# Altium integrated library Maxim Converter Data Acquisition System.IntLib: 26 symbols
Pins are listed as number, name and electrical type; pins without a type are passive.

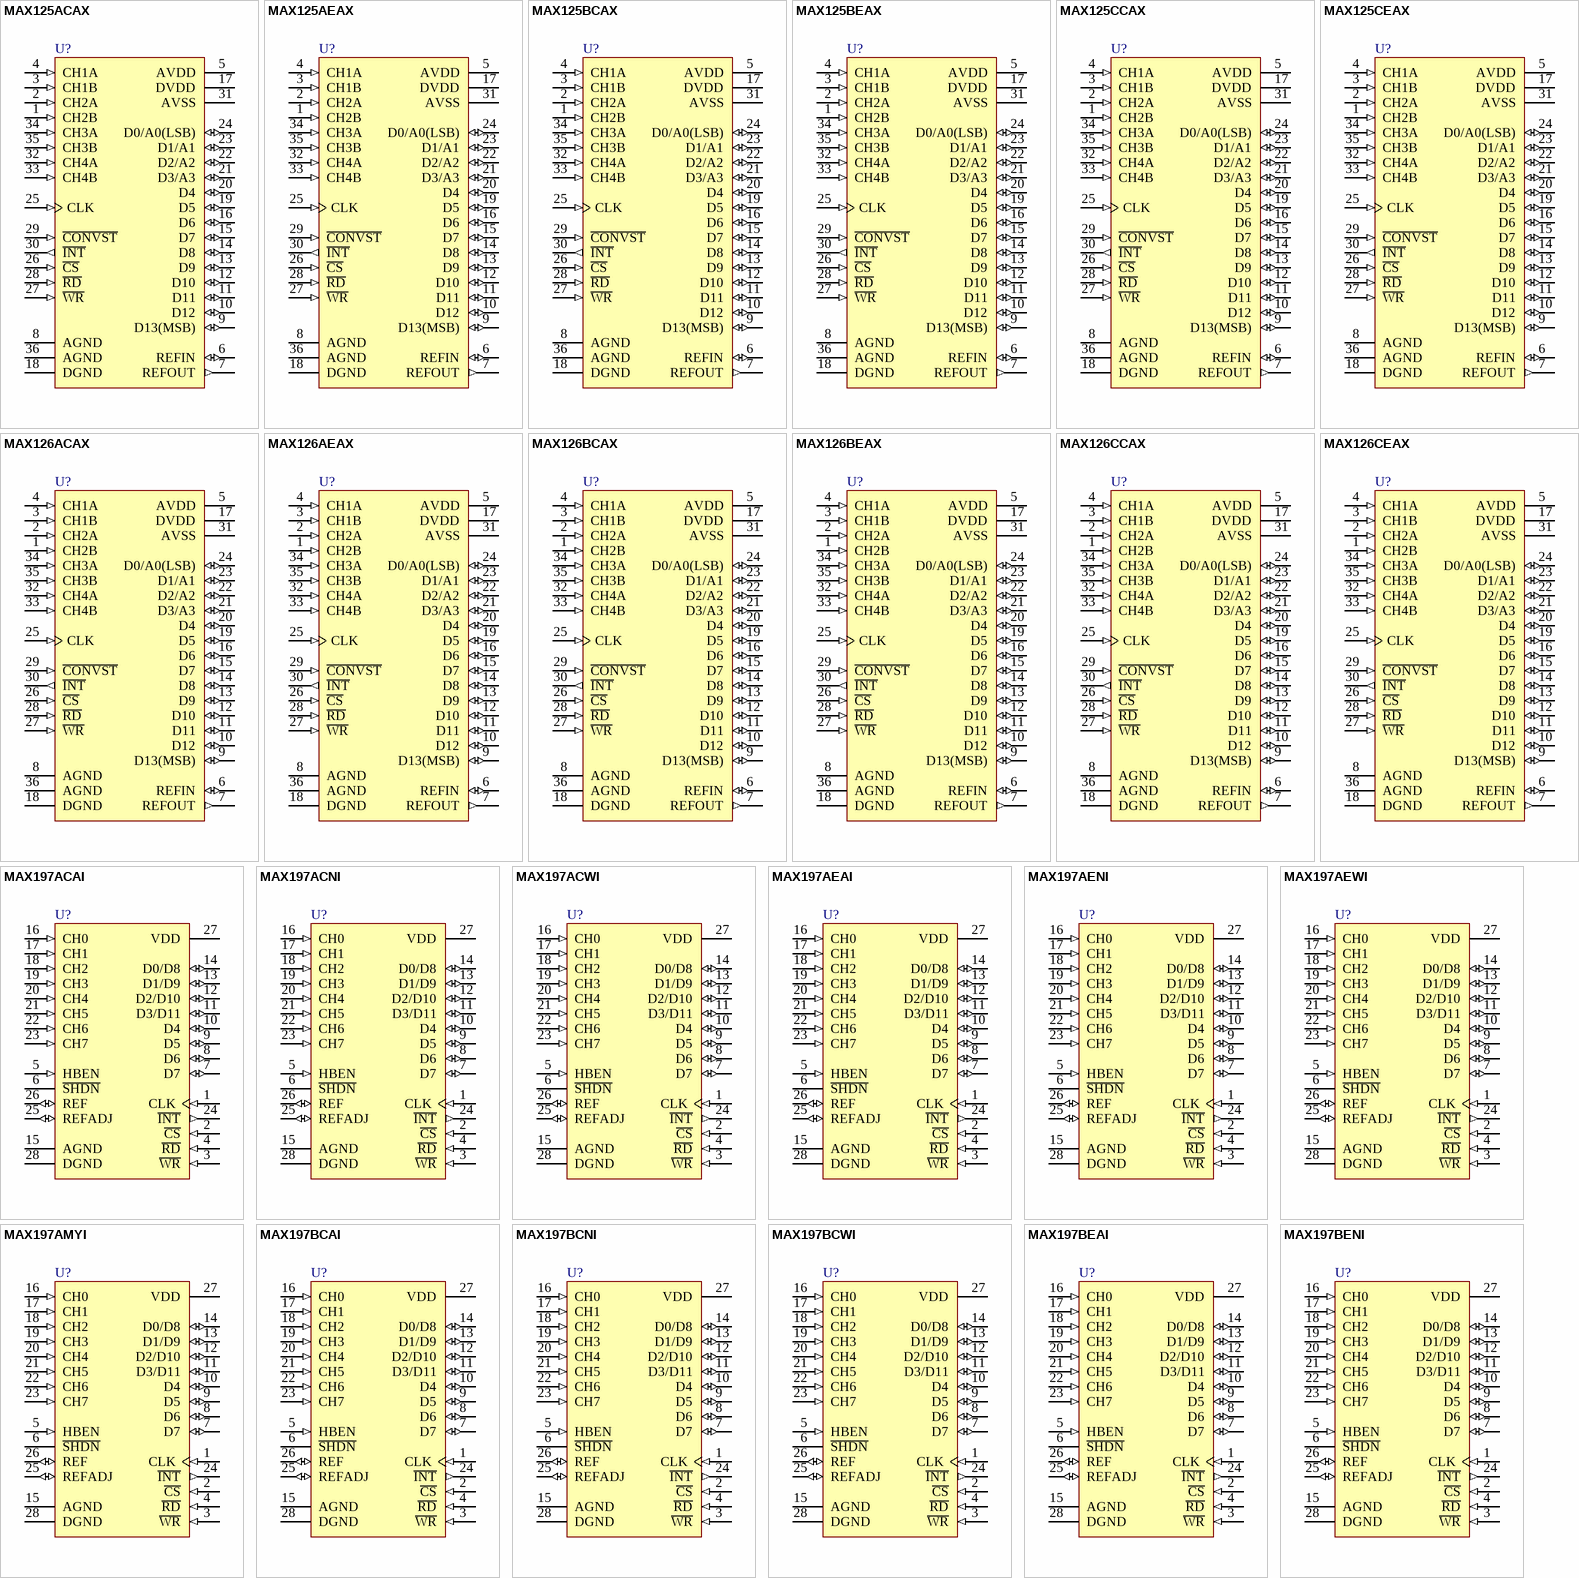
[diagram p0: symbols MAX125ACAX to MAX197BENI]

## MAX125ACAX
designator U?
2x4-Channel, Simultaneous-Sampling 14-Bit DAS
footprint SSOP36_N (SOP, 36-Leads, Body 15.4x7.5mm, Pitch 0.8mm, IPC Medium Density)
footprint SSOP36_L (SOP, 36-Leads, Body 15.4x7.5mm, Pitch 0.8mm, IPC High Density)
footprint SSOP36_M (SOP, 36-Leads, Body 15.4x7.5mm, Pitch 0.8mm, IPC Low Density)
3D model SSOP36 (36-Pin Small Outline Package 0.8 mm Pitch)
pins: 1 CH2B (in), 2 CH2A (in), 3 CH1B (in), 4 CH1A (in), 5 AVDD (power), 6 REFIN (io), 7 REFOUT (out), 8 AGND (power), 9 D13(MSB) (io), 10 D12 (io), 11 D11 (io), 12 D10 (io), 13 D9 (io), 14 D8 (io), 15 D7 (io), 16 D6 (io), 17 DVDD (power), 18 DGND (power), 19 D5 (io), 20 D4 (io), 21 D3/A3 (io), 22 D2/A2 (io), 23 D1/A1 (io), 24 D0/A0(LSB) (io), 25 CLK (in), 26 ~{CS} (in), 27 ~{WR} (in), 28 ~{RD} (in), 29 ~{CONVST} (in), 30 ~{INT} (out), 31 AVSS (power), 32 CH4A (in), 33 CH4B (in), 34 CH3A (in), 35 CH3B (in), 36 AGND (power)

## MAX125AEAX
designator U?
2x4-Channel, Simultaneous-Sampling 14-Bit DAS
footprint SSOP36_N (SOP, 36-Leads, Body 15.4x7.5mm, Pitch 0.8mm, IPC Medium Density)
footprint SSOP36_L (SOP, 36-Leads, Body 15.4x7.5mm, Pitch 0.8mm, IPC High Density)
footprint SSOP36_M (SOP, 36-Leads, Body 15.4x7.5mm, Pitch 0.8mm, IPC Low Density)
3D model SSOP36 (36-Pin Small Outline Package 0.8 mm Pitch)
pins: 1 CH2B (in), 2 CH2A (in), 3 CH1B (in), 4 CH1A (in), 5 AVDD (power), 6 REFIN (io), 7 REFOUT (out), 8 AGND (power), 9 D13(MSB) (io), 10 D12 (io), 11 D11 (io), 12 D10 (io), 13 D9 (io), 14 D8 (io), 15 D7 (io), 16 D6 (io), 17 DVDD (power), 18 DGND (power), 19 D5 (io), 20 D4 (io), 21 D3/A3 (io), 22 D2/A2 (io), 23 D1/A1 (io), 24 D0/A0(LSB) (io), 25 CLK (in), 26 ~{CS} (in), 27 ~{WR} (in), 28 ~{RD} (in), 29 ~{CONVST} (in), 30 ~{INT} (out), 31 AVSS (power), 32 CH4A (in), 33 CH4B (in), 34 CH3A (in), 35 CH3B (in), 36 AGND (power)

## MAX125BCAX
designator U?
2x4-Channel, Simultaneous-Sampling 14-Bit DAS
footprint SSOP36_N (SOP, 36-Leads, Body 15.4x7.5mm, Pitch 0.8mm, IPC Medium Density)
footprint SSOP36_L (SOP, 36-Leads, Body 15.4x7.5mm, Pitch 0.8mm, IPC High Density)
footprint SSOP36_M (SOP, 36-Leads, Body 15.4x7.5mm, Pitch 0.8mm, IPC Low Density)
3D model SSOP36 (36-Pin Small Outline Package 0.8 mm Pitch)
pins: 1 CH2B (in), 2 CH2A (in), 3 CH1B (in), 4 CH1A (in), 5 AVDD (power), 6 REFIN (io), 7 REFOUT (out), 8 AGND (power), 9 D13(MSB) (io), 10 D12 (io), 11 D11 (io), 12 D10 (io), 13 D9 (io), 14 D8 (io), 15 D7 (io), 16 D6 (io), 17 DVDD (power), 18 DGND (power), 19 D5 (io), 20 D4 (io), 21 D3/A3 (io), 22 D2/A2 (io), 23 D1/A1 (io), 24 D0/A0(LSB) (io), 25 CLK (in), 26 ~{CS} (in), 27 ~{WR} (in), 28 ~{RD} (in), 29 ~{CONVST} (in), 30 ~{INT} (out), 31 AVSS (power), 32 CH4A (in), 33 CH4B (in), 34 CH3A (in), 35 CH3B (in), 36 AGND (power)

## MAX125BEAX
designator U?
2x4-Channel, Simultaneous-Sampling 14-Bit DAS
footprint SSOP36_N (SOP, 36-Leads, Body 15.4x7.5mm, Pitch 0.8mm, IPC Medium Density)
footprint SSOP36_L (SOP, 36-Leads, Body 15.4x7.5mm, Pitch 0.8mm, IPC High Density)
footprint SSOP36_M (SOP, 36-Leads, Body 15.4x7.5mm, Pitch 0.8mm, IPC Low Density)
3D model SSOP36 (36-Pin Small Outline Package 0.8 mm Pitch)
pins: 1 CH2B (in), 2 CH2A (in), 3 CH1B (in), 4 CH1A (in), 5 AVDD (power), 6 REFIN (io), 7 REFOUT (out), 8 AGND (power), 9 D13(MSB) (io), 10 D12 (io), 11 D11 (io), 12 D10 (io), 13 D9 (io), 14 D8 (io), 15 D7 (io), 16 D6 (io), 17 DVDD (power), 18 DGND (power), 19 D5 (io), 20 D4 (io), 21 D3/A3 (io), 22 D2/A2 (io), 23 D1/A1 (io), 24 D0/A0(LSB) (io), 25 CLK (in), 26 ~{CS} (in), 27 ~{WR} (in), 28 ~{RD} (in), 29 ~{CONVST} (in), 30 ~{INT} (out), 31 AVSS (power), 32 CH4A (in), 33 CH4B (in), 34 CH3A (in), 35 CH3B (in), 36 AGND (power)

## MAX125CCAX
designator U?
2x4-Channel, Simultaneous-Sampling 14-Bit DAS
footprint SSOP36_N (SOP, 36-Leads, Body 15.4x7.5mm, Pitch 0.8mm, IPC Medium Density)
footprint SSOP36_L (SOP, 36-Leads, Body 15.4x7.5mm, Pitch 0.8mm, IPC High Density)
footprint SSOP36_M (SOP, 36-Leads, Body 15.4x7.5mm, Pitch 0.8mm, IPC Low Density)
3D model SSOP36 (36-Pin Small Outline Package 0.8 mm Pitch)
pins: 1 CH2B (in), 2 CH2A (in), 3 CH1B (in), 4 CH1A (in), 5 AVDD (power), 6 REFIN (io), 7 REFOUT (out), 8 AGND (power), 9 D13(MSB) (io), 10 D12 (io), 11 D11 (io), 12 D10 (io), 13 D9 (io), 14 D8 (io), 15 D7 (io), 16 D6 (io), 17 DVDD (power), 18 DGND (power), 19 D5 (io), 20 D4 (io), 21 D3/A3 (io), 22 D2/A2 (io), 23 D1/A1 (io), 24 D0/A0(LSB) (io), 25 CLK (in), 26 ~{CS} (in), 27 ~{WR} (in), 28 ~{RD} (in), 29 ~{CONVST} (in), 30 ~{INT} (out), 31 AVSS (power), 32 CH4A (in), 33 CH4B (in), 34 CH3A (in), 35 CH3B (in), 36 AGND (power)

## MAX125CEAX
designator U?
2x4-Channel, Simultaneous-Sampling 14-Bit DAS
footprint SSOP36_N (SOP, 36-Leads, Body 15.4x7.5mm, Pitch 0.8mm, IPC Medium Density)
footprint SSOP36_L (SOP, 36-Leads, Body 15.4x7.5mm, Pitch 0.8mm, IPC High Density)
footprint SSOP36_M (SOP, 36-Leads, Body 15.4x7.5mm, Pitch 0.8mm, IPC Low Density)
3D model SSOP36 (36-Pin Small Outline Package 0.8 mm Pitch)
pins: 1 CH2B (in), 2 CH2A (in), 3 CH1B (in), 4 CH1A (in), 5 AVDD (power), 6 REFIN (io), 7 REFOUT (out), 8 AGND (power), 9 D13(MSB) (io), 10 D12 (io), 11 D11 (io), 12 D10 (io), 13 D9 (io), 14 D8 (io), 15 D7 (io), 16 D6 (io), 17 DVDD (power), 18 DGND (power), 19 D5 (io), 20 D4 (io), 21 D3/A3 (io), 22 D2/A2 (io), 23 D1/A1 (io), 24 D0/A0(LSB) (io), 25 CLK (in), 26 ~{CS} (in), 27 ~{WR} (in), 28 ~{RD} (in), 29 ~{CONVST} (in), 30 ~{INT} (out), 31 AVSS (power), 32 CH4A (in), 33 CH4B (in), 34 CH3A (in), 35 CH3B (in), 36 AGND (power)

## MAX126ACAX
designator U?
2x4-Channel, Simultaneous-Sampling 14-Bit DAS
footprint SSOP36_N (SOP, 36-Leads, Body 15.4x7.5mm, Pitch 0.8mm, IPC Medium Density)
footprint SSOP36_L (SOP, 36-Leads, Body 15.4x7.5mm, Pitch 0.8mm, IPC High Density)
footprint SSOP36_M (SOP, 36-Leads, Body 15.4x7.5mm, Pitch 0.8mm, IPC Low Density)
3D model SSOP36 (36-Pin Small Outline Package 0.8 mm Pitch)
pins: 1 CH2B (in), 2 CH2A (in), 3 CH1B (in), 4 CH1A (in), 5 AVDD (power), 6 REFIN (io), 7 REFOUT (out), 8 AGND (power), 9 D13(MSB) (io), 10 D12 (io), 11 D11 (io), 12 D10 (io), 13 D9 (io), 14 D8 (io), 15 D7 (io), 16 D6 (io), 17 DVDD (power), 18 DGND (power), 19 D5 (io), 20 D4 (io), 21 D3/A3 (io), 22 D2/A2 (io), 23 D1/A1 (io), 24 D0/A0(LSB) (io), 25 CLK (in), 26 ~{CS} (in), 27 ~{WR} (in), 28 ~{RD} (in), 29 ~{CONVST} (in), 30 ~{INT} (out), 31 AVSS (power), 32 CH4A (in), 33 CH4B (in), 34 CH3A (in), 35 CH3B (in), 36 AGND (power)

## MAX126AEAX
designator U?
2x4-Channel, Simultaneous-Sampling 14-Bit DAS
footprint SSOP36_N (SOP, 36-Leads, Body 15.4x7.5mm, Pitch 0.8mm, IPC Medium Density)
footprint SSOP36_L (SOP, 36-Leads, Body 15.4x7.5mm, Pitch 0.8mm, IPC High Density)
footprint SSOP36_M (SOP, 36-Leads, Body 15.4x7.5mm, Pitch 0.8mm, IPC Low Density)
3D model SSOP36 (36-Pin Small Outline Package 0.8 mm Pitch)
pins: 1 CH2B (in), 2 CH2A (in), 3 CH1B (in), 4 CH1A (in), 5 AVDD (power), 6 REFIN (io), 7 REFOUT (out), 8 AGND (power), 9 D13(MSB) (io), 10 D12 (io), 11 D11 (io), 12 D10 (io), 13 D9 (io), 14 D8 (io), 15 D7 (io), 16 D6 (io), 17 DVDD (power), 18 DGND (power), 19 D5 (io), 20 D4 (io), 21 D3/A3 (io), 22 D2/A2 (io), 23 D1/A1 (io), 24 D0/A0(LSB) (io), 25 CLK (in), 26 ~{CS} (in), 27 ~{WR} (in), 28 ~{RD} (in), 29 ~{CONVST} (in), 30 ~{INT} (out), 31 AVSS (power), 32 CH4A (in), 33 CH4B (in), 34 CH3A (in), 35 CH3B (in), 36 AGND (power)

## MAX126BCAX
designator U?
2x4-Channel, Simultaneous-Sampling 14-Bit DAS
footprint SSOP36_N (SOP, 36-Leads, Body 15.4x7.5mm, Pitch 0.8mm, IPC Medium Density)
footprint SSOP36_L (SOP, 36-Leads, Body 15.4x7.5mm, Pitch 0.8mm, IPC High Density)
footprint SSOP36_M (SOP, 36-Leads, Body 15.4x7.5mm, Pitch 0.8mm, IPC Low Density)
3D model SSOP36 (36-Pin Small Outline Package 0.8 mm Pitch)
pins: 1 CH2B (in), 2 CH2A (in), 3 CH1B (in), 4 CH1A (in), 5 AVDD (power), 6 REFIN (io), 7 REFOUT (out), 8 AGND (power), 9 D13(MSB) (io), 10 D12 (io), 11 D11 (io), 12 D10 (io), 13 D9 (io), 14 D8 (io), 15 D7 (io), 16 D6 (io), 17 DVDD (power), 18 DGND (power), 19 D5 (io), 20 D4 (io), 21 D3/A3 (io), 22 D2/A2 (io), 23 D1/A1 (io), 24 D0/A0(LSB) (io), 25 CLK (in), 26 ~{CS} (in), 27 ~{WR} (in), 28 ~{RD} (in), 29 ~{CONVST} (in), 30 ~{INT} (out), 31 AVSS (power), 32 CH4A (in), 33 CH4B (in), 34 CH3A (in), 35 CH3B (in), 36 AGND (power)

## MAX126BEAX
designator U?
2x4-Channel, Simultaneous-Sampling 14-Bit DAS
footprint SSOP36_N (SOP, 36-Leads, Body 15.4x7.5mm, Pitch 0.8mm, IPC Medium Density)
footprint SSOP36_L (SOP, 36-Leads, Body 15.4x7.5mm, Pitch 0.8mm, IPC High Density)
footprint SSOP36_M (SOP, 36-Leads, Body 15.4x7.5mm, Pitch 0.8mm, IPC Low Density)
3D model SSOP36 (36-Pin Small Outline Package 0.8 mm Pitch)
pins: 1 CH2B (in), 2 CH2A (in), 3 CH1B (in), 4 CH1A (in), 5 AVDD (power), 6 REFIN (io), 7 REFOUT (out), 8 AGND (power), 9 D13(MSB) (io), 10 D12 (io), 11 D11 (io), 12 D10 (io), 13 D9 (io), 14 D8 (io), 15 D7 (io), 16 D6 (io), 17 DVDD (power), 18 DGND (power), 19 D5 (io), 20 D4 (io), 21 D3/A3 (io), 22 D2/A2 (io), 23 D1/A1 (io), 24 D0/A0(LSB) (io), 25 CLK (in), 26 ~{CS} (in), 27 ~{WR} (in), 28 ~{RD} (in), 29 ~{CONVST} (in), 30 ~{INT} (out), 31 AVSS (power), 32 CH4A (in), 33 CH4B (in), 34 CH3A (in), 35 CH3B (in), 36 AGND (power)

## MAX126CCAX
designator U?
2x4-Channel, Simultaneous-Sampling 14-Bit DAS
footprint SSOP36_N (SOP, 36-Leads, Body 15.4x7.5mm, Pitch 0.8mm, IPC Medium Density)
footprint SSOP36_L (SOP, 36-Leads, Body 15.4x7.5mm, Pitch 0.8mm, IPC High Density)
footprint SSOP36_M (SOP, 36-Leads, Body 15.4x7.5mm, Pitch 0.8mm, IPC Low Density)
3D model SSOP36 (36-Pin Small Outline Package 0.8 mm Pitch)
pins: 1 CH2B (in), 2 CH2A (in), 3 CH1B (in), 4 CH1A (in), 5 AVDD (power), 6 REFIN (io), 7 REFOUT (out), 8 AGND (power), 9 D13(MSB) (io), 10 D12 (io), 11 D11 (io), 12 D10 (io), 13 D9 (io), 14 D8 (io), 15 D7 (io), 16 D6 (io), 17 DVDD (power), 18 DGND (power), 19 D5 (io), 20 D4 (io), 21 D3/A3 (io), 22 D2/A2 (io), 23 D1/A1 (io), 24 D0/A0(LSB) (io), 25 CLK (in), 26 ~{CS} (in), 27 ~{WR} (in), 28 ~{RD} (in), 29 ~{CONVST} (in), 30 ~{INT} (out), 31 AVSS (power), 32 CH4A (in), 33 CH4B (in), 34 CH3A (in), 35 CH3B (in), 36 AGND (power)

## MAX126CEAX
designator U?
2x4-Channel, Simultaneous-Sampling 14-Bit DAS
footprint SSOP36_N (SOP, 36-Leads, Body 15.4x7.5mm, Pitch 0.8mm, IPC Medium Density)
footprint SSOP36_L (SOP, 36-Leads, Body 15.4x7.5mm, Pitch 0.8mm, IPC High Density)
footprint SSOP36_M (SOP, 36-Leads, Body 15.4x7.5mm, Pitch 0.8mm, IPC Low Density)
3D model SSOP36 (36-Pin Small Outline Package 0.8 mm Pitch)
pins: 1 CH2B (in), 2 CH2A (in), 3 CH1B (in), 4 CH1A (in), 5 AVDD (power), 6 REFIN (io), 7 REFOUT (out), 8 AGND (power), 9 D13(MSB) (io), 10 D12 (io), 11 D11 (io), 12 D10 (io), 13 D9 (io), 14 D8 (io), 15 D7 (io), 16 D6 (io), 17 DVDD (power), 18 DGND (power), 19 D5 (io), 20 D4 (io), 21 D3/A3 (io), 22 D2/A2 (io), 23 D1/A1 (io), 24 D0/A0(LSB) (io), 25 CLK (in), 26 ~{CS} (in), 27 ~{WR} (in), 28 ~{RD} (in), 29 ~{CONVST} (in), 30 ~{INT} (out), 31 AVSS (power), 32 CH4A (in), 33 CH4B (in), 34 CH3A (in), 35 CH3B (in), 36 AGND (power)

## MAX197ACAI
designator U?
Single +5V 12-Bit DAS with 8+4 Bus Interface
footprint SSOP28_N (SOP, 28-Leads, Body 10.2x5.3mm, Pitch 0.65mm, IPC Medium Density)
footprint SSOP28_L (SOP, 28-Leads, Body 10.2x5.3mm, Pitch 0.65mm, IPC High Density)
footprint SSOP28_M (SOP, 28-Leads, Body 10.2x5.3mm, Pitch 0.65mm, IPC Low Density)
3D model SSOP28 (28-Pin Small Outline Package 0.65 mm Pitch)
pins: 1 CLK (in), 2 ~{CS} (in), 3 ~{WR} (in), 4 ~{RD} (in), 5 HBEN (in), 6 ~{SHDN}, 7 D7 (io), 8 D6 (io), 9 D5 (io), 10 D4 (io), 11 D3/D11 (io), 12 D2/D10 (io), 13 D1/D9 (io), 14 D0/D8 (io), 15 AGND (power), 16 CH0 (in), 17 CH1 (in), 18 CH2 (in), 19 CH3 (in), 20 CH4 (in), 21 CH5 (in), 22 CH6 (in), 23 CH7 (in), 24 ~{INT} (out), 25 REFADJ (io), 26 REF (io), 27 VDD (power), 28 DGND (power)

## MAX197ACNI
designator U?
Single +5V 12-Bit DAS with 8+4 Bus Interface
footprint NI28 (DIP, 28-Leads, Row Spacing 7.62mm, Pitch 2.54mm, Body 34.8x7.24mm)
3D model NI28 (DIP, 28-Pin, Row Spacing 7.62 mm, Pitch 2.54 mm)
pins: 1 CLK (in), 2 ~{CS} (in), 3 ~{WR} (in), 4 ~{RD} (in), 5 HBEN (in), 6 ~{SHDN}, 7 D7 (io), 8 D6 (io), 9 D5 (io), 10 D4 (io), 11 D3/D11 (io), 12 D2/D10 (io), 13 D1/D9 (io), 14 D0/D8 (io), 15 AGND (power), 16 CH0 (in), 17 CH1 (in), 18 CH2 (in), 19 CH3 (in), 20 CH4 (in), 21 CH5 (in), 22 CH6 (in), 23 CH7 (in), 24 ~{INT} (out), 25 REFADJ (io), 26 REF (io), 27 VDD (power), 28 DGND (power)

## MAX197ACWI
designator U?
Single +5V 12-Bit DAS with 8+4 Bus Interface
footprint WSO28_N (SOIC, 28-Leads, Body 17.9x7.5mm, Pitch 1.27mm, IPC Medium Density)
footprint WSO28_L (SOIC, 28-Leads, Body 17.9x7.5mm, Pitch 1.27mm, IPC High Density)
footprint WSO28_M (SOIC, 28-Leads, Body 17.9x7.5mm, Pitch 1.27mm, IPC Low Density)
3D model WSO28 (28-Pin Small Outline Integrated Circuit 1.27 mm Pitch)
pins: 1 CLK (in), 2 ~{CS} (in), 3 ~{WR} (in), 4 ~{RD} (in), 5 HBEN (in), 6 ~{SHDN}, 7 D7 (io), 8 D6 (io), 9 D5 (io), 10 D4 (io), 11 D3/D11 (io), 12 D2/D10 (io), 13 D1/D9 (io), 14 D0/D8 (io), 15 AGND (power), 16 CH0 (in), 17 CH1 (in), 18 CH2 (in), 19 CH3 (in), 20 CH4 (in), 21 CH5 (in), 22 CH6 (in), 23 CH7 (in), 24 ~{INT} (out), 25 REFADJ (io), 26 REF (io), 27 VDD (power), 28 DGND (power)

## MAX197AEAI
designator U?
Single +5V 12-Bit DAS with 8+4 Bus Interface
footprint SSOP28_N (SOP, 28-Leads, Body 10.2x5.3mm, Pitch 0.65mm, IPC Medium Density)
footprint SSOP28_L (SOP, 28-Leads, Body 10.2x5.3mm, Pitch 0.65mm, IPC High Density)
footprint SSOP28_M (SOP, 28-Leads, Body 10.2x5.3mm, Pitch 0.65mm, IPC Low Density)
3D model SSOP28 (28-Pin Small Outline Package 0.65 mm Pitch)
pins: 1 CLK (in), 2 ~{CS} (in), 3 ~{WR} (in), 4 ~{RD} (in), 5 HBEN (in), 6 ~{SHDN}, 7 D7 (io), 8 D6 (io), 9 D5 (io), 10 D4 (io), 11 D3/D11 (io), 12 D2/D10 (io), 13 D1/D9 (io), 14 D0/D8 (io), 15 AGND (power), 16 CH0 (in), 17 CH1 (in), 18 CH2 (in), 19 CH3 (in), 20 CH4 (in), 21 CH5 (in), 22 CH6 (in), 23 CH7 (in), 24 ~{INT} (out), 25 REFADJ (io), 26 REF (io), 27 VDD (power), 28 DGND (power)

## MAX197AENI
designator U?
Single +5V 12-Bit DAS with 8+4 Bus Interface
footprint NI28 (DIP, 28-Leads, Row Spacing 7.62mm, Pitch 2.54mm, Body 34.8x7.24mm)
3D model NI28 (DIP, 28-Pin, Row Spacing 7.62 mm, Pitch 2.54 mm)
pins: 1 CLK (in), 2 ~{CS} (in), 3 ~{WR} (in), 4 ~{RD} (in), 5 HBEN (in), 6 ~{SHDN}, 7 D7 (io), 8 D6 (io), 9 D5 (io), 10 D4 (io), 11 D3/D11 (io), 12 D2/D10 (io), 13 D1/D9 (io), 14 D0/D8 (io), 15 AGND (power), 16 CH0 (in), 17 CH1 (in), 18 CH2 (in), 19 CH3 (in), 20 CH4 (in), 21 CH5 (in), 22 CH6 (in), 23 CH7 (in), 24 ~{INT} (out), 25 REFADJ (io), 26 REF (io), 27 VDD (power), 28 DGND (power)

## MAX197AEWI
designator U?
Single +5V 12-Bit DAS with 8+4 Bus Interface
footprint WSO28_N (SOIC, 28-Leads, Body 17.9x7.5mm, Pitch 1.27mm, IPC Medium Density)
footprint WSO28_L (SOIC, 28-Leads, Body 17.9x7.5mm, Pitch 1.27mm, IPC High Density)
footprint WSO28_M (SOIC, 28-Leads, Body 17.9x7.5mm, Pitch 1.27mm, IPC Low Density)
3D model WSO28 (28-Pin Small Outline Integrated Circuit 1.27 mm Pitch)
pins: 1 CLK (in), 2 ~{CS} (in), 3 ~{WR} (in), 4 ~{RD} (in), 5 HBEN (in), 6 ~{SHDN}, 7 D7 (io), 8 D6 (io), 9 D5 (io), 10 D4 (io), 11 D3/D11 (io), 12 D2/D10 (io), 13 D1/D9 (io), 14 D0/D8 (io), 15 AGND (power), 16 CH0 (in), 17 CH1 (in), 18 CH2 (in), 19 CH3 (in), 20 CH4 (in), 21 CH5 (in), 22 CH6 (in), 23 CH7 (in), 24 ~{INT} (out), 25 REFADJ (io), 26 REF (io), 27 VDD (power), 28 DGND (power)

## MAX197AMYI
designator U?
Single +5V 12-Bit DAS with 8+4 Bus Interface
footprint DI28A (DIP, 28-Leads, Row Spacing 15.24mm, Pitch 2.54mm, Body 37.15x14.1mm)
3D model DI28A (DIP, 28-Pin, Row Spacing 15.24 mm, Pitch 2.54 mm)
pins: 1 CLK (in), 2 ~{CS} (in), 3 ~{WR} (in), 4 ~{RD} (in), 5 HBEN (in), 6 ~{SHDN}, 7 D7 (io), 8 D6 (io), 9 D5 (io), 10 D4 (io), 11 D3/D11 (io), 12 D2/D10 (io), 13 D1/D9 (io), 14 D0/D8 (io), 15 AGND (power), 16 CH0 (in), 17 CH1 (in), 18 CH2 (in), 19 CH3 (in), 20 CH4 (in), 21 CH5 (in), 22 CH6 (in), 23 CH7 (in), 24 ~{INT} (out), 25 REFADJ (io), 26 REF (io), 27 VDD (power), 28 DGND (power)

## MAX197BCAI
designator U?
Single +5V 12-Bit DAS with 8+4 Bus Interface
footprint SSOP28_N (SOP, 28-Leads, Body 10.2x5.3mm, Pitch 0.65mm, IPC Medium Density)
footprint SSOP28_L (SOP, 28-Leads, Body 10.2x5.3mm, Pitch 0.65mm, IPC High Density)
footprint SSOP28_M (SOP, 28-Leads, Body 10.2x5.3mm, Pitch 0.65mm, IPC Low Density)
3D model SSOP28 (28-Pin Small Outline Package 0.65 mm Pitch)
pins: 1 CLK (in), 2 ~{CS} (in), 3 ~{WR} (in), 4 ~{RD} (in), 5 HBEN (in), 6 ~{SHDN}, 7 D7 (io), 8 D6 (io), 9 D5 (io), 10 D4 (io), 11 D3/D11 (io), 12 D2/D10 (io), 13 D1/D9 (io), 14 D0/D8 (io), 15 AGND (power), 16 CH0 (in), 17 CH1 (in), 18 CH2 (in), 19 CH3 (in), 20 CH4 (in), 21 CH5 (in), 22 CH6 (in), 23 CH7 (in), 24 ~{INT} (out), 25 REFADJ (io), 26 REF (io), 27 VDD (power), 28 DGND (power)

## MAX197BCNI
designator U?
Single +5V 12-Bit DAS with 8+4 Bus Interface
footprint NI28 (DIP, 28-Leads, Row Spacing 7.62mm, Pitch 2.54mm, Body 34.8x7.24mm)
3D model NI28 (DIP, 28-Pin, Row Spacing 7.62 mm, Pitch 2.54 mm)
pins: 1 CLK (in), 2 ~{CS} (in), 3 ~{WR} (in), 4 ~{RD} (in), 5 HBEN (in), 6 ~{SHDN}, 7 D7 (io), 8 D6 (io), 9 D5 (io), 10 D4 (io), 11 D3/D11 (io), 12 D2/D10 (io), 13 D1/D9 (io), 14 D0/D8 (io), 15 AGND (power), 16 CH0 (in), 17 CH1 (in), 18 CH2 (in), 19 CH3 (in), 20 CH4 (in), 21 CH5 (in), 22 CH6 (in), 23 CH7 (in), 24 ~{INT} (out), 25 REFADJ (io), 26 REF (io), 27 VDD (power), 28 DGND (power)

## MAX197BCWI
designator U?
Single +5V 12-Bit DAS with 8+4 Bus Interface
footprint WSO28_N (SOIC, 28-Leads, Body 17.9x7.5mm, Pitch 1.27mm, IPC Medium Density)
footprint WSO28_L (SOIC, 28-Leads, Body 17.9x7.5mm, Pitch 1.27mm, IPC High Density)
footprint WSO28_M (SOIC, 28-Leads, Body 17.9x7.5mm, Pitch 1.27mm, IPC Low Density)
3D model WSO28 (28-Pin Small Outline Integrated Circuit 1.27 mm Pitch)
pins: 1 CLK (in), 2 ~{CS} (in), 3 ~{WR} (in), 4 ~{RD} (in), 5 HBEN (in), 6 ~{SHDN}, 7 D7 (io), 8 D6 (io), 9 D5 (io), 10 D4 (io), 11 D3/D11 (io), 12 D2/D10 (io), 13 D1/D9 (io), 14 D0/D8 (io), 15 AGND (power), 16 CH0 (in), 17 CH1 (in), 18 CH2 (in), 19 CH3 (in), 20 CH4 (in), 21 CH5 (in), 22 CH6 (in), 23 CH7 (in), 24 ~{INT} (out), 25 REFADJ (io), 26 REF (io), 27 VDD (power), 28 DGND (power)

## MAX197BEAI
designator U?
Single +5V 12-Bit DAS with 8+4 Bus Interface
footprint SSOP28_N (SOP, 28-Leads, Body 10.2x5.3mm, Pitch 0.65mm, IPC Medium Density)
footprint SSOP28_L (SOP, 28-Leads, Body 10.2x5.3mm, Pitch 0.65mm, IPC High Density)
footprint SSOP28_M (SOP, 28-Leads, Body 10.2x5.3mm, Pitch 0.65mm, IPC Low Density)
3D model SSOP28 (28-Pin Small Outline Package 0.65 mm Pitch)
pins: 1 CLK (in), 2 ~{CS} (in), 3 ~{WR} (in), 4 ~{RD} (in), 5 HBEN (in), 6 ~{SHDN}, 7 D7 (io), 8 D6 (io), 9 D5 (io), 10 D4 (io), 11 D3/D11 (io), 12 D2/D10 (io), 13 D1/D9 (io), 14 D0/D8 (io), 15 AGND (power), 16 CH0 (in), 17 CH1 (in), 18 CH2 (in), 19 CH3 (in), 20 CH4 (in), 21 CH5 (in), 22 CH6 (in), 23 CH7 (in), 24 ~{INT} (out), 25 REFADJ (io), 26 REF (io), 27 VDD (power), 28 DGND (power)

## MAX197BENI
designator U?
Single +5V 12-Bit DAS with 8+4 Bus Interface
footprint NI28 (DIP, 28-Leads, Row Spacing 7.62mm, Pitch 2.54mm, Body 34.8x7.24mm)
3D model NI28 (DIP, 28-Pin, Row Spacing 7.62 mm, Pitch 2.54 mm)
pins: 1 CLK (in), 2 ~{CS} (in), 3 ~{WR} (in), 4 ~{RD} (in), 5 HBEN (in), 6 ~{SHDN}, 7 D7 (io), 8 D6 (io), 9 D5 (io), 10 D4 (io), 11 D3/D11 (io), 12 D2/D10 (io), 13 D1/D9 (io), 14 D0/D8 (io), 15 AGND (power), 16 CH0 (in), 17 CH1 (in), 18 CH2 (in), 19 CH3 (in), 20 CH4 (in), 21 CH5 (in), 22 CH6 (in), 23 CH7 (in), 24 ~{INT} (out), 25 REFADJ (io), 26 REF (io), 27 VDD (power), 28 DGND (power)

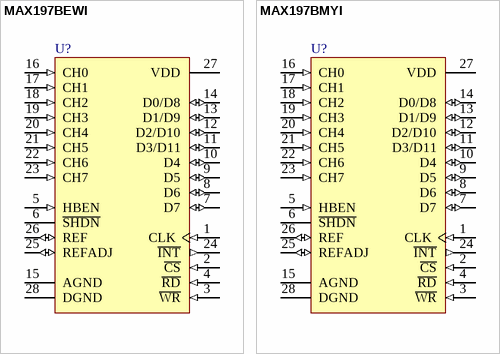
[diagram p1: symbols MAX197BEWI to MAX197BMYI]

## MAX197BEWI
designator U?
Single +5V 12-Bit DAS with 8+4 Bus Interface
footprint WSO28_N (SOIC, 28-Leads, Body 17.9x7.5mm, Pitch 1.27mm, IPC Medium Density)
footprint WSO28_L (SOIC, 28-Leads, Body 17.9x7.5mm, Pitch 1.27mm, IPC High Density)
footprint WSO28_M (SOIC, 28-Leads, Body 17.9x7.5mm, Pitch 1.27mm, IPC Low Density)
3D model WSO28 (28-Pin Small Outline Integrated Circuit 1.27 mm Pitch)
pins: 1 CLK (in), 2 ~{CS} (in), 3 ~{WR} (in), 4 ~{RD} (in), 5 HBEN (in), 6 ~{SHDN}, 7 D7 (io), 8 D6 (io), 9 D5 (io), 10 D4 (io), 11 D3/D11 (io), 12 D2/D10 (io), 13 D1/D9 (io), 14 D0/D8 (io), 15 AGND (power), 16 CH0 (in), 17 CH1 (in), 18 CH2 (in), 19 CH3 (in), 20 CH4 (in), 21 CH5 (in), 22 CH6 (in), 23 CH7 (in), 24 ~{INT} (out), 25 REFADJ (io), 26 REF (io), 27 VDD (power), 28 DGND (power)

## MAX197BMYI
designator U?
Single +5V 12-Bit DAS with 8+4 Bus Interface
footprint DI28A (DIP, 28-Leads, Row Spacing 15.24mm, Pitch 2.54mm, Body 37.15x14.1mm)
3D model DI28A (DIP, 28-Pin, Row Spacing 15.24 mm, Pitch 2.54 mm)
pins: 1 CLK (in), 2 ~{CS} (in), 3 ~{WR} (in), 4 ~{RD} (in), 5 HBEN (in), 6 ~{SHDN}, 7 D7 (io), 8 D6 (io), 9 D5 (io), 10 D4 (io), 11 D3/D11 (io), 12 D2/D10 (io), 13 D1/D9 (io), 14 D0/D8 (io), 15 AGND (power), 16 CH0 (in), 17 CH1 (in), 18 CH2 (in), 19 CH3 (in), 20 CH4 (in), 21 CH5 (in), 22 CH6 (in), 23 CH7 (in), 24 ~{INT} (out), 25 REFADJ (io), 26 REF (io), 27 VDD (power), 28 DGND (power)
